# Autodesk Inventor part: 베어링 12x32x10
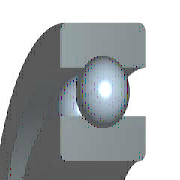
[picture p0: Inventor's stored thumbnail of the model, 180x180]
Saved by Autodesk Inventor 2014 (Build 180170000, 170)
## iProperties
IsCustomPart: 1
Created: 2012-02
Part Number: 베어링 12x32x10
Material: 강철, 연강
Description: 깊은 그루브 볼 베어링
Document SubType Name: Modeling
Standard: KS B 2023
Designer: test
Standards Organization: KS
Language: ko-KR
Size Designation: 6201 - 12 x 32 x 10
Categories: <MemberInstance><Categories><Category DisplayName="샤프트 부품" InternalName="7f7aeb1f-a693-4053-b835-cee3144e0d98" Mnemonic="SHFT"><Category DisplayName="베어링" Inter
Density: 1 g/cm^3
Appearance: 노란색
Author: test
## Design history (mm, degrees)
sketch "스케치" dims "d0" = 5.2 (= -0.26 x WD + 0.26 x BD)
  geometry: L1 (2.4, 11)-(7.6, 11); L2 (5, 11)-(5, 8.4); L3 (5, 11)-(5, 13.6); L4 (3.068, 9.26)-(0, 9.26); L5 (0, 6)-(10, 6); L6 (3.068, 12.74)-(0, 12.74); L7 (0, 16)-(10, 16); L8 (10, 6)-(10, 9.26); L9 (6.932, 9.26)-(10, 9.26); L10 (6.932, 12.74)-(10, 12.74); L11 (10, 16)-(10, 12.74); L12 (-1.4, 0)-(8.4, 0) reference; L13 (0, -0.3)-(0, 5.3) reference
  constraints: 22 end point, 4 point on line, 2 collinear, 2 perpendicular, 2 symmetric about line, 1 midpoint, 1 parallel, 14 other
  dimensions: "d9" = 12 diameter of L5 L12 (= WD); "d11" = 32 diameter of L7 L12 (= BD); "d12" = 10 distance between parallel lines of L8 L13 (= KB); "d13" = 18.52 diameter of L9 L12 (= 0.326 x BD + 0.674 x WD)
revolve "본체" stored, may be unused: angle "d6" = 90 deg
revolve "볼" stored, may be unused: angle "d7" = 90 deg
pattern_circular "IDS_ARRAYBALL[SIMPL:T]" dims angle "d3" = 360 deg
body "Solid1"
fillet "모깎기1" dims "d1" = 0.6 (= KRS)
other parameters: "WD" = 12 [user parameter; used in 5 equation terms], "BD" = 32 [user parameter; used in 5 equation terms], "KB" = 10 [user parameter; used in 1 equation term], "KRS" = 0.6 [user parameter; used in 1 equation term], "d4" = 0, "d5" = 0, "d8" = 0, "d14" = 0, "d15" = 0, "BBA" = 0 [user parameter], "BC0" = 3100000 [user parameter], "BC" = 6890000 [user parameter], "BR" = 16 (= 0.5 x BD) [user parameter], "WR" = 6 (= 0.5 x WD) [user parameter]
